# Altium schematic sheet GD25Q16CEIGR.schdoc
size 127 x 101 mm
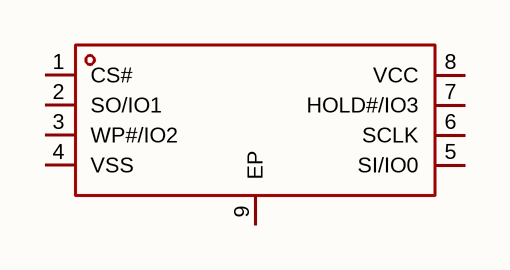
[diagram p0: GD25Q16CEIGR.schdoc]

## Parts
U?  gd25q16ceigr  [USON-8_L3.0-W2.0-P0.50-BL-EP-1]  (value not drawn)

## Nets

Not connected (* = marked no-connect by the designer): U? 1(CS#) 2(SO/IO1) 3(WP#/IO2) 4(VSS) 5(SI/IO0) 6(SCLK) 7(HOLD#/IO3) 8(VCC) 9(EP)

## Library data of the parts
U? = gd25q16ceigr: 接口类型:SPI;存储容量:16Mbit;时钟频率(fc):120MHz;; Manufacturer: GigaDevice(兆易创新); AddInBom: yes; Interface: SPI; Memory Size: 16Mbit; Clock Frequency: 120MHz; Voltage - Supply: 2.7V~3.6V; Standby Supply Current: 1uA; Program / Erase Cycles: 100000次; Page Programming Time (Tpp): 600us; Block Erase Time(tBE): 250ms@(64KB); Data Retention - TDR (Year): 20年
